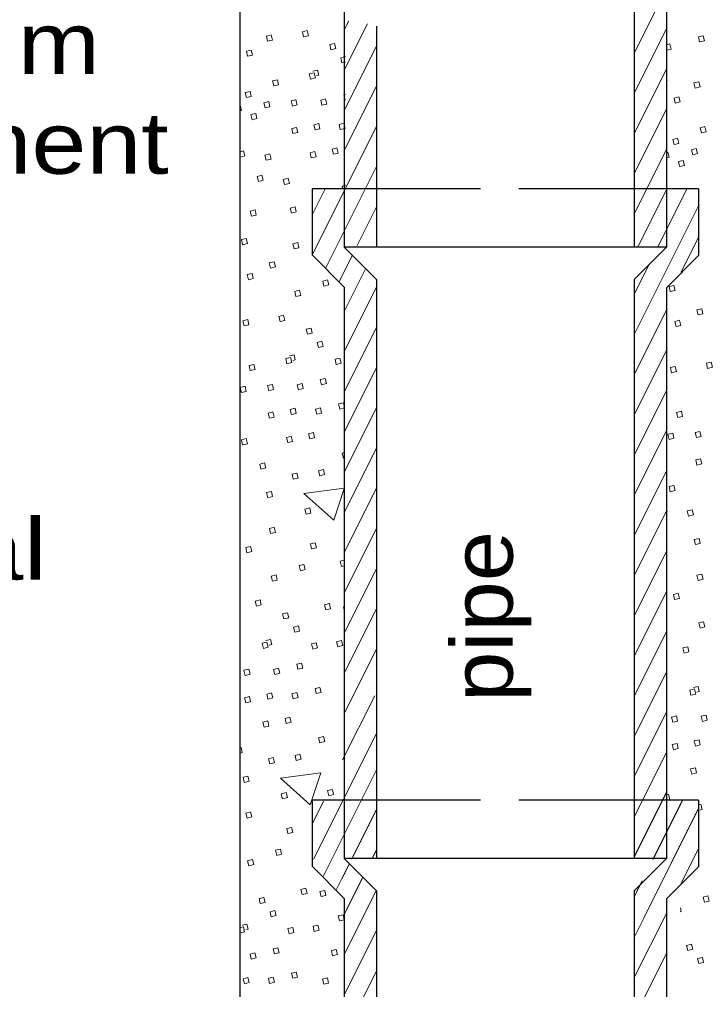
# Model space of a CAD drawing. Extents: x 750.7 to 784.7, y 860.1 to 882.1.
# Drawn here: x 760.016 to 761.807, y 870.002 to 872.527 of the extents above; entities that cross this region are included whole.
import ezdxf
from ezdxf.enums import TextEntityAlignment as Align

# ---------------------------------------------------------------- set-up
doc = ezdxf.new("R2010")
doc.units = 0
doc.header["$LTSCALE"] = 0.064
doc.linetypes.add('LONG_DASHED', pattern=[7.5, 6, -1.5])
doc.layers.add('1', color=7, linetype='Continuous', lineweight=13)

msp = doc.modelspace()

# ---------------------------------------------------------------- linework, layer by layer
at = {"layer": '1', "lineweight": 25}
for p, q in [((760.59067, 862.95208), (760.59067, 875.03808)), ((760.862, 873.40767), (760.862, 871.93358)), ((761.7, 873.40617), (761.7, 871.93358)), ((760.94558, 872.50942), (760.94558, 872.24317)), ((760.94567, 872.24317), (760.94567, 871.93358)), ((760.77825, 872.08592), (760.77825, 871.93358)), ((760.862, 872.08592), (760.77825, 872.08592)), ((760.77825, 872.08592), (760.77825, 871.91383)), ((761.78367, 872.08592), (761.7, 872.08592)), ((761.78367, 872.08592), (761.78367, 871.91225)), ((761.78367, 872.08592), (761.78367, 871.91225)), ((761.7, 871.93358), (760.862, 871.93358)), ((761.7, 871.93358), (760.862, 871.93358)), ((760.862, 871.93358), (760.94567, 871.84992)), ((761.7, 871.93358), (761.61633, 871.84992)), ((760.77825, 871.91383), (760.862, 871.83017)), ((761.78367, 871.91225), (761.7, 871.82858)), ((760.94567, 871.84992), (760.94567, 870.34292)), ((761.61633, 871.84992), (761.61633, 870.343)), ((760.862, 871.83017), (760.862, 870.343)), ((761.7, 871.82858), (761.7, 870.343)), ((760.862, 870.49533), (760.77825, 870.49533)), ((760.77825, 870.49533), (760.77825, 870.34292)), ((760.77825, 870.49533), (760.77825, 870.32325)), ((761.78367, 870.49533), (761.7, 870.49533)), ((761.78367, 870.49533), (761.7, 870.49533)), ((761.78367, 870.49533), (761.78367, 870.343)), ((761.78367, 870.49533), (761.78367, 870.32167)), ((761.7, 870.343), (760.862, 870.34292)), ((761.7, 870.343), (760.862, 870.34292)), ((760.862, 870.343), (760.94567, 870.25925)), ((761.7, 870.343), (761.61633, 870.25925)), ((760.77825, 870.32325), (760.862, 870.2395)), ((761.78367, 870.32167), (761.7, 870.238)), ((760.94567, 870.25925), (760.94567, 868.74475)), ((761.61633, 870.25925), (761.61633, 868.74333)), ((760.862, 870.2395), (760.862, 868.74367)), ((761.7, 870.238), (761.7, 868.74367))]:
    msp.add_line(p, q, dxfattribs=at)
at = {"layer": '1'}
for p, q in [((761.61633, 872.43917), (761.7, 872.60658)), ((760.86192, 872.49908), (760.87383, 872.52292)), ((760.86192, 872.39442), (760.9225, 872.5155)), ((761.61633, 872.33458), (761.7, 872.502)), ((760.862, 872.28983), (760.94567, 872.45725)), ((761.7, 872.46058), (761.70933, 872.46283)), ((760.78033, 872.39158), (760.7925, 872.39442)), ((761.61633, 872.23), (761.7, 872.39742)), ((760.94567, 872.35267), (760.862, 872.18533)), ((761.7025, 872.36875), (761.7, 872.36842)), ((761.7, 872.36117), (761.7025, 872.36875)), ((760.59067, 872.303), (760.59125, 872.30308)), ((761.61633, 872.12533), (761.7, 872.29275)), ((760.77867, 871.914), (760.94567, 872.248)), ((760.59067, 872.18233), (760.6, 872.18458)), ((761.61633, 872.02075), (761.7, 872.18817)), ((761.7, 872.18017), (761.70392, 872.18117)), ((760.81325, 871.87858), (760.94567, 872.1435)), ((760.81233, 872.086), (760.77825, 872.01783)), ((760.86192, 872.08592), (760.77825, 872.08592)), ((760.79833, 872.08658), (760.79983, 872.08692)), ((760.79983, 872.08692), (760.79983, 872.08658)), ((761.62475, 871.933), (761.7, 872.08358)), ((761.67775, 871.93442), (761.7535, 872.08592)), ((760.89533, 871.93817), (760.94567, 872.03883)), ((761.61633, 871.707), (761.78367, 872.04175)), ((761.73825, 871.869), (761.78367, 871.96)), ((760.94542, 871.93383), (760.94567, 871.93425)), ((760.84842, 871.84442), (760.882, 871.9115)), ((760.862, 871.76683), (760.91667, 871.87625)), ((761.61633, 871.81158), (761.656, 871.89083)), ((760.862, 871.66225), (760.94567, 871.82958)), ((761.61633, 871.60233), (761.7, 871.76975)), ((760.862, 871.55758), (760.94567, 871.725)), ((760.719, 871.65092), (760.73117, 871.65383)), ((761.61633, 871.49775), (761.7, 871.66517)), ((760.862, 871.453), (760.94567, 871.62042)), ((761.61633, 871.39317), (761.7, 871.56058)), ((760.85975, 871.52917), (760.862, 871.52008)), ((760.862, 871.34842), (760.94567, 871.51583)), ((761.61633, 871.28858), (761.7, 871.45592)), ((760.862, 871.24383), (760.94567, 871.41117)), ((761.61633, 871.18392), (761.7, 871.35133)), ((760.862, 871.13917), (760.94567, 871.30658)), ((761.61633, 871.07933), (761.7, 871.24675)), ((760.862, 871.03458), (760.94567, 871.202)), ((761.61633, 870.97475), (761.7, 871.14217)), ((760.862, 870.93), (760.94567, 871.09742)), ((761.61633, 870.87017), (761.7, 871.0375)), ((760.862, 870.82542), (760.94567, 870.99275)), ((760.65775, 870.91033), (760.66983, 870.91325)), ((761.61633, 870.7655), (761.7, 870.93292)), ((760.862, 870.72075), (760.94567, 870.88817)), ((761.61633, 870.66092), (761.7, 870.82833)), ((761.77042, 870.78842), (761.7825, 870.79125)), ((760.8575, 870.59967), (760.94117, 870.767)), ((761.61633, 870.55633), (761.7, 870.72375)), ((760.78192, 870.34133), (760.94642, 870.67042)), ((760.59067, 870.6315), (760.59317, 870.63208)), ((761.61633, 870.45175), (761.7, 870.61917)), ((760.80692, 870.29683), (760.94567, 870.57433)), ((761.61633, 870.34842), (761.7, 870.51583)), ((761.61633, 870.34708), (761.7, 870.5145)), ((761.7, 870.50875), (761.70583, 870.51008)), ((760.778, 870.43292), (760.80783, 870.49267)), ((761.66508, 870.34133), (761.74208, 870.49533)), ((761.66558, 870.34108), (761.74275, 870.49533)), ((761.7855, 870.48275), (761.78983, 870.48375)), ((760.88158, 870.343), (760.94567, 870.47108)), ((760.88158, 870.34167), (760.94567, 870.46975)), ((761.61633, 870.13792), (761.78367, 870.47267)), ((761.641, 870.18842), (761.78367, 870.474)), ((760.93433, 870.34383), (760.94567, 870.3665)), ((760.93475, 870.34333), (760.94567, 870.36517)), ((761.73825, 870.27842), (761.78367, 870.36942)), ((761.76483, 870.33042), (761.78367, 870.36808)), ((760.85625, 870.29092), (760.8755, 870.32942)), ((760.84092, 870.26158), (760.87408, 870.328)), ((760.862, 870.19775), (760.90933, 870.29258)), ((760.86783, 870.21075), (760.90925, 870.29375)), ((761.61633, 870.2425), (761.6375, 870.28483)), ((761.62358, 870.25825), (761.636, 870.28308)), ((760.862, 870.09317), (760.94567, 870.26058)), ((761.61633, 870.03333), (761.7, 870.20067)), ((760.59067, 870.16367), (760.59942, 870.16575)), ((760.59642, 870.16975), (760.6085, 870.17267)), ((760.862, 869.98858), (760.94567, 870.15592)), ((761.61633, 869.92867), (761.7, 870.09608)), ((760.862, 869.88392), (760.94567, 870.05133))]:
    msp.add_line(p, q, dxfattribs=at)
at = {"layer": '1', "linetype": 'LONG_DASHED', "lineweight": 25}
for p, q in [((761.7, 872.08592), (760.86192, 872.08592)), ((761.7, 872.08592), (760.862, 872.08592)), ((761.7, 870.49533), (760.862, 870.49533)), ((761.7, 870.49533), (760.862, 870.49533))]:
    msp.add_line(p, q, dxfattribs=at)
at = {"layer": '1', "lineweight": 25}
msp.add_lwpolyline([(761.7, 873.51108), (761.61633, 873.42742), (761.61633, 871.93358)], dxfattribs=at)
at = {"layer": '1'}
for points in [[(760.67183, 872.48617), (760.675, 872.47292), (760.66242, 872.46992), (760.65925, 872.48317)], [(760.7655, 872.49742), (760.76867, 872.48417), (760.75608, 872.48117), (760.75292, 872.49442)], [(761.79583, 872.48425), (761.79908, 872.471), (761.7865, 872.468), (761.78333, 872.48125)], [(760.83675, 872.46408), (760.83992, 872.45083), (760.82733, 872.44783), (760.82417, 872.46108)], [(760.61975, 872.447), (760.623, 872.43375), (760.61042, 872.43075), (760.60717, 872.444)], [(760.78333, 872.38758), (760.78658, 872.37433), (760.774, 872.37133), (760.77083, 872.38458)], [(760.68783, 872.36958), (760.69108, 872.35642), (760.6785, 872.35342), (760.67533, 872.36667)], [(761.7845, 872.36425), (761.78767, 872.351), (761.77508, 872.348), (761.77192, 872.36125)], [(760.61675, 872.33925), (760.62, 872.326), (760.60742, 872.323), (760.60417, 872.33625)], [(761.73242, 872.325), (761.73567, 872.31175), (761.72308, 872.30875), (761.71992, 872.322)], [(760.66517, 872.31267), (760.66833, 872.29942), (760.65583, 872.29642), (760.65258, 872.30967)], [(760.73617, 872.31733), (760.73933, 872.30408), (760.72675, 872.30108), (760.72358, 872.31433)], [(760.81325, 872.31958), (760.8165, 872.30642), (760.80392, 872.30342), (760.80075, 872.31667)], [(760.63133, 872.28183), (760.6345, 872.26858), (760.62192, 872.26558), (760.61875, 872.27883)], [(760.79525, 872.25542), (760.79842, 872.24217), (760.78583, 872.23917), (760.78267, 872.25242)], [(760.861, 872.25633), (760.86417, 872.24308), (760.85158, 872.24008), (760.84842, 872.25333)], [(761.8005, 872.24767), (761.80375, 872.23442), (761.79117, 872.23142), (761.788, 872.24467)], [(760.73767, 872.24575), (760.74092, 872.2325), (760.72833, 872.2295), (760.72517, 872.24275)], [(761.72942, 872.21725), (761.73267, 872.204), (761.72008, 872.201), (761.71692, 872.21425)], [(760.66808, 872.1765), (760.67133, 872.16325), (760.65875, 872.16025), (760.65558, 872.1735)], [(760.78542, 872.1825), (760.78858, 872.16925), (760.776, 872.16625), (760.77283, 872.1795)], [(760.84292, 872.19208), (760.84608, 872.17892), (760.8335, 872.17592), (760.83033, 872.18908)], [(761.77783, 872.19067), (761.781, 872.17742), (761.7685, 872.17442), (761.76525, 872.18767)], [(761.744, 872.15983), (761.74717, 872.14667), (761.73458, 872.14367), (761.73142, 872.15692)], [(760.64767, 872.12125), (760.65083, 872.108), (760.63833, 872.105), (760.63508, 872.11825)], [(760.71583, 872.11325), (760.719, 872.1), (760.70642, 872.097), (760.70325, 872.11025)], [(760.62983, 872.03075), (760.633, 872.0175), (760.6205, 872.0145), (760.61725, 872.02775)], [(760.73367, 872.03883), (760.73683, 872.02558), (760.72433, 872.02258), (760.72108, 872.03583)], [(760.60683, 871.95658), (760.61, 871.94333), (760.59742, 871.94042), (760.59425, 871.95358)], [(760.74083, 871.94583), (760.744, 871.93258), (760.7315, 871.92958), (760.72825, 871.94283)], [(760.67933, 871.89592), (760.68258, 871.88267), (760.67, 871.87967), (760.66683, 871.89292)], [(760.62183, 871.86558), (760.62508, 871.85233), (760.6125, 871.84933), (760.60933, 871.86258)], [(760.81825, 871.84892), (760.82142, 871.83567), (760.80892, 871.83267), (760.80567, 871.84592)], [(760.74567, 871.82175), (760.74883, 871.8085), (760.73625, 871.80558), (760.73308, 871.81875)], [(761.7195, 871.83467), (761.72267, 871.82142), (761.71008, 871.81842), (761.70692, 871.83167)], [(761.79208, 871.77392), (761.79525, 871.76067), (761.78267, 871.75767), (761.7795, 871.77092)], [(760.6105, 871.74558), (760.61367, 871.73233), (760.60108, 871.72933), (760.59792, 871.74258)], [(760.70417, 871.75683), (760.70733, 871.74358), (760.69483, 871.74058), (760.69158, 871.75383)], [(761.7345, 871.74367), (761.73775, 871.73042), (761.72517, 871.72742), (761.722, 871.74067)], [(760.77542, 871.7235), (760.77858, 871.71025), (760.766, 871.70725), (760.76283, 871.7205)], [(760.80392, 871.68908), (760.80708, 871.67592), (760.7945, 871.67292), (760.79133, 871.68617)], [(760.72208, 871.647), (760.72525, 871.63375), (760.71267, 871.63075), (760.7095, 871.644)], [(760.85033, 871.64517), (760.85358, 871.63192), (760.841, 871.62892), (760.83783, 871.64217)], [(760.6265, 871.629), (760.62975, 871.61583), (760.61717, 871.61283), (760.614, 871.626)], [(761.72317, 871.62358), (761.72633, 871.61042), (761.71375, 871.60742), (761.71058, 871.62067)], [(761.81683, 871.63483), (761.82, 871.62158), (761.8075, 871.61858), (761.80425, 871.63183)], [(760.81208, 871.59242), (760.81525, 871.57917), (760.80275, 871.57617), (760.7995, 871.58942)], [(760.60383, 871.57208), (760.607, 871.55883), (760.5945, 871.55583), (760.59125, 871.56908)], [(760.67483, 871.57675), (760.678, 871.5635), (760.66542, 871.5605), (760.66225, 871.57375)], [(760.75192, 871.579), (760.75517, 871.56583), (760.74258, 871.56283), (760.73942, 871.576)], [(760.79967, 871.51575), (760.80283, 871.5025), (760.79025, 871.4995), (760.78708, 871.51275)], [(760.67633, 871.50517), (760.67958, 871.49192), (760.667, 871.48892), (760.66383, 871.50217)], [(760.73392, 871.51483), (760.73708, 871.50158), (760.7245, 871.49858), (760.72133, 871.51183)], [(761.73917, 871.50708), (761.74242, 871.49383), (761.72983, 871.49083), (761.72667, 871.50408)], [(760.72408, 871.44192), (760.72725, 871.42867), (760.71467, 871.42567), (760.7115, 871.43892)], [(760.78158, 871.4515), (760.78475, 871.43825), (760.77225, 871.43525), (760.769, 871.4485)], [(761.7165, 871.45008), (761.71967, 871.43683), (761.70717, 871.43383), (761.70392, 871.44708)], [(761.7875, 871.45475), (761.79067, 871.4415), (761.77808, 871.4385), (761.77492, 871.45175)], [(760.60675, 871.43592), (760.61, 871.42267), (760.59742, 871.41967), (760.59425, 871.43292)], [(760.6545, 871.37267), (760.65767, 871.35942), (760.64508, 871.35642), (760.64192, 871.36967)], [(761.789, 871.38317), (761.79225, 871.37), (761.77967, 871.367), (761.7765, 871.38025)], [(760.7385, 871.34633), (760.74167, 871.33308), (760.72908, 871.33008), (760.72592, 871.34333)], [(760.80767, 871.35533), (760.81083, 871.34208), (760.79825, 871.33908), (760.79508, 871.35233)], [(761.71942, 871.314), (761.72267, 871.30075), (761.71008, 871.29775), (761.70692, 871.311)], [(760.67233, 871.29825), (760.6755, 871.285), (760.663, 871.282), (760.65975, 871.29525)], [(760.772, 871.25542), (760.77517, 871.24225), (760.76267, 871.23925), (760.75942, 871.2525)], [(761.76717, 871.25067), (761.77033, 871.23742), (761.75775, 871.23442), (761.75458, 871.24767)], [(760.6795, 871.20525), (760.68267, 871.192), (760.67017, 871.189), (760.66692, 871.20225)], [(760.78608, 871.165), (760.78933, 871.15175), (760.77675, 871.14875), (760.77358, 871.162)], [(761.785, 871.17633), (761.78825, 871.16308), (761.77567, 871.16008), (761.77242, 871.17333)], [(760.61808, 871.15533), (760.62125, 871.14208), (760.60867, 871.13908), (760.6055, 871.15233)], [(760.75692, 871.10833), (760.76008, 871.09508), (760.74758, 871.09208), (760.74433, 871.10533)], [(760.68433, 871.08117), (760.6875, 871.06792), (760.675, 871.06492), (760.67175, 871.07817)], [(761.79217, 871.08333), (761.79542, 871.07008), (761.78283, 871.06708), (761.77958, 871.08033)], [(760.64283, 871.01625), (760.646, 871.003), (760.6335, 871), (760.63025, 871.01325)], [(761.73075, 871.03333), (761.73392, 871.02008), (761.72133, 871.01708), (761.71817, 871.03033)], [(760.82308, 871.0065), (760.82625, 870.99325), (760.81367, 870.99025), (760.8105, 871.0035)], [(760.71408, 870.98292), (760.71725, 870.96967), (760.70467, 870.96667), (760.7015, 870.97992)], [(760.74258, 870.9485), (760.74575, 870.93525), (760.73317, 870.93233), (760.73, 870.9455)], [(761.797, 870.95925), (761.80017, 870.946), (761.78767, 870.943), (761.78442, 870.95625)], [(760.85458, 870.9105), (760.85775, 870.89725), (760.84517, 870.89433), (760.842, 870.9075)], [(760.66075, 870.90633), (760.66392, 870.89317), (760.65133, 870.89017), (760.64817, 870.90342)], [(760.78908, 870.90458), (760.79225, 870.89133), (760.77967, 870.88833), (760.7765, 870.90158)], [(761.7555, 870.89425), (761.75867, 870.881), (761.74617, 870.878), (761.74292, 870.89125)], [(760.6135, 870.83617), (760.61667, 870.82292), (760.60417, 870.81992), (760.60092, 870.83317)], [(760.69058, 870.83842), (760.69383, 870.82517), (760.68125, 870.82217), (760.67808, 870.83542)], [(760.75075, 870.85183), (760.75392, 870.83858), (760.74142, 870.83558), (760.73817, 870.84883)], [(760.79842, 870.7885), (760.80167, 870.77533), (760.78908, 870.77233), (760.78592, 870.78558)], [(761.77342, 870.78442), (761.77658, 870.77117), (761.764, 870.76817), (761.76083, 870.78142)], [(760.615, 870.76458), (760.61825, 870.75133), (760.60567, 870.74833), (760.6025, 870.76158)], [(760.67258, 870.77425), (760.67575, 870.761), (760.66317, 870.758), (760.66, 870.77125)], [(760.73833, 870.77517), (760.7415, 870.76192), (760.72892, 870.75892), (760.72575, 870.77217)], [(760.72025, 870.71092), (760.72342, 870.69767), (760.71092, 870.69467), (760.70767, 870.70792)], [(761.72617, 870.71417), (761.72933, 870.70092), (761.71683, 870.69792), (761.71358, 870.71117)], [(761.80333, 870.7165), (761.8065, 870.70325), (761.79392, 870.70025), (761.79075, 870.7135)], [(760.66275, 870.70133), (760.66592, 870.68808), (760.65333, 870.68508), (760.65017, 870.69833)], [(760.80775, 870.66075), (760.81092, 870.6475), (760.79842, 870.6445), (760.79517, 870.65775)], [(761.72775, 870.64258), (761.73092, 870.62933), (761.71833, 870.62642), (761.71517, 870.63958)], [(761.78525, 870.65225), (761.78842, 870.639), (761.77583, 870.636), (761.77267, 870.64925)], [(760.74633, 870.61475), (760.7495, 870.6015), (760.73692, 870.5985), (760.73375, 870.61175)], [(760.67717, 870.60575), (760.68033, 870.5925), (760.66775, 870.5895), (760.66458, 870.60275)], [(760.611, 870.55767), (760.61425, 870.54442), (760.60167, 870.54142), (760.5985, 870.55467)], [(760.80092, 870.56658), (760.6955, 870.55258), (760.77308, 870.48292)], [(761.77542, 870.57933), (761.77858, 870.56608), (761.766, 870.56308), (761.76283, 870.57633)], [(760.71067, 870.51483), (760.71383, 870.50167), (760.70133, 870.49867), (760.69808, 870.51183)], [(760.83083, 870.52292), (760.83408, 870.50967), (760.8215, 870.50667), (760.81833, 870.51992)], [(760.61817, 870.46467), (760.62142, 870.45142), (760.60883, 870.44842), (760.60567, 870.46167)], [(760.72483, 870.42442), (760.728, 870.41117), (760.71542, 870.40817), (760.71225, 870.42142)], [(760.69558, 870.36775), (760.69883, 870.3545), (760.68625, 870.3515), (760.68308, 870.36475)], [(760.623, 870.34058), (760.62617, 870.32733), (760.61367, 870.32433), (760.61042, 870.33758)], [(760.76175, 870.26592), (760.76492, 870.25267), (760.75233, 870.24967), (760.74917, 870.26292)], [(760.81108, 870.2605), (760.81425, 870.24725), (760.80167, 870.24425), (760.7985, 870.2575)], [(760.65275, 870.24225), (760.65592, 870.22908), (760.64342, 870.22608), (760.64017, 870.23933)], [(761.80825, 870.24583), (761.8115, 870.23258), (761.79892, 870.22958), (761.79575, 870.24283)], [(760.68125, 870.20792), (760.68442, 870.19467), (760.67192, 870.19167), (760.66867, 870.20492)], [(760.85875, 870.19717), (760.86192, 870.184), (760.84942, 870.181), (760.84617, 870.19425)], [(760.72775, 870.164), (760.73092, 870.15075), (760.71833, 870.14775), (760.71517, 870.161)], [(760.79325, 870.16992), (760.79642, 870.15667), (760.78383, 870.15375), (760.78067, 870.16692)], [(760.68942, 870.11125), (760.69258, 870.098), (760.68008, 870.095), (760.67683, 870.10825)], [(760.84092, 870.10667), (760.84408, 870.09342), (760.83158, 870.09042), (760.82833, 870.10367)], [(761.76542, 870.12033), (761.76858, 870.10708), (761.75608, 870.10408), (761.75283, 870.11733)], [(760.62933, 870.09783), (760.6325, 870.08458), (760.61992, 870.08158), (760.61675, 870.09483)], [(761.79392, 870.086), (761.79708, 870.07275), (761.78458, 870.06975), (761.78133, 870.083)], [(760.61125, 870.03367), (760.61442, 870.02042), (760.60183, 870.01742), (760.59867, 870.03067)], [(760.677, 870.03458), (760.68017, 870.02133), (760.66767, 870.01833), (760.66442, 870.03158)], [(760.73708, 870.04792), (760.74033, 870.03467), (760.72775, 870.03175), (760.72458, 870.04492)], [(760.81792, 870.03258), (760.82108, 870.01933), (760.8085, 870.01633), (760.80533, 870.02958)]]:
    msp.add_lwpolyline(points, close=True, dxfattribs=at)
for points in [[(761.70933, 872.46283), (761.7125, 872.44958), (761.7, 872.44658)], [(760.865, 872.41567), (760.85583, 872.4135), (760.85267, 872.42675), (760.86492, 872.42967)], [(760.7925, 872.39442), (760.79567, 872.38117), (760.78933, 872.37967)], [(760.86533, 872.31708), (760.864, 872.31675), (760.86083, 872.33), (760.86525, 872.33108)], [(760.59125, 872.30308), (760.5945, 872.28992), (760.59067, 872.289)], [(760.6, 872.18458), (760.60317, 872.17133), (760.59067, 872.16833)], [(761.70392, 872.18117), (761.70717, 872.16792), (761.7, 872.16617)], [(760.8575, 872.08842), (760.85642, 872.09292), (760.866, 872.09525)], [(761.78367, 872.0425), (761.784, 872.04133), (761.78367, 872.04125)], [(760.73117, 871.65383), (760.73433, 871.64058), (760.728, 871.63908)], [(760.862, 871.51567), (760.85042, 871.51292), (760.84717, 871.52617), (760.85975, 871.52917)], [(760.862, 871.38567), (760.85967, 871.38508), (760.8565, 871.39833), (760.862, 871.39967)], [(760.862, 871.30717), (760.75683, 871.29317), (760.83442, 871.2235), (760.862, 871.30625)], [(761.7, 871.25458), (761.70225, 871.2455), (761.7, 871.24492)], [(760.862, 871.10525), (760.85433, 871.10342), (760.85117, 871.11667), (760.862, 871.11925)], [(760.862, 870.98925), (760.85983, 870.99808), (760.862, 870.99858)], [(760.66983, 870.91325), (760.673, 870.9), (760.66667, 870.89842)], [(761.7825, 870.79125), (761.78567, 870.778), (761.77933, 870.7765)], [(760.59317, 870.63208), (760.59633, 870.61883), (760.59067, 870.6175)], [(761.70583, 870.51008), (761.709, 870.49683), (761.70267, 870.49533)], [(761.78983, 870.48375), (761.793, 870.4705), (761.78733, 870.46917)], [(761.7365, 870.21525), (761.73883, 870.20542), (761.73617, 870.20475)], [(760.59942, 870.16575), (760.60258, 870.1525), (760.59067, 870.14967)], [(760.6085, 870.17267), (760.61175, 870.15942), (760.60533, 870.15783)]]:
    msp.add_lwpolyline(points, dxfattribs=at)

# ---------------------------------------------------------------- texts
at = {"layer": '1', "width": 1.2}
for s, p in [('minimum', (759.70558, 872.38492)), ('encasement', (759.70558, 872.12492))]:
    msp.add_text(s, height=0.16, dxfattribs=at).set_placement(p, align=Align.CENTER)
at = {"layer": '1', "width": 1.3}
msp.add_text('[200] nominal', height=0.16, dxfattribs=at).set_placement((758.41875, 871.06858))
at = {"layer": '1', "width": 1.1}
msp.add_text('pipe', height=0.16, rotation=90, dxfattribs=at).set_placement((761.30017, 870.75075))

doc.saveas('drawing.dxf')
